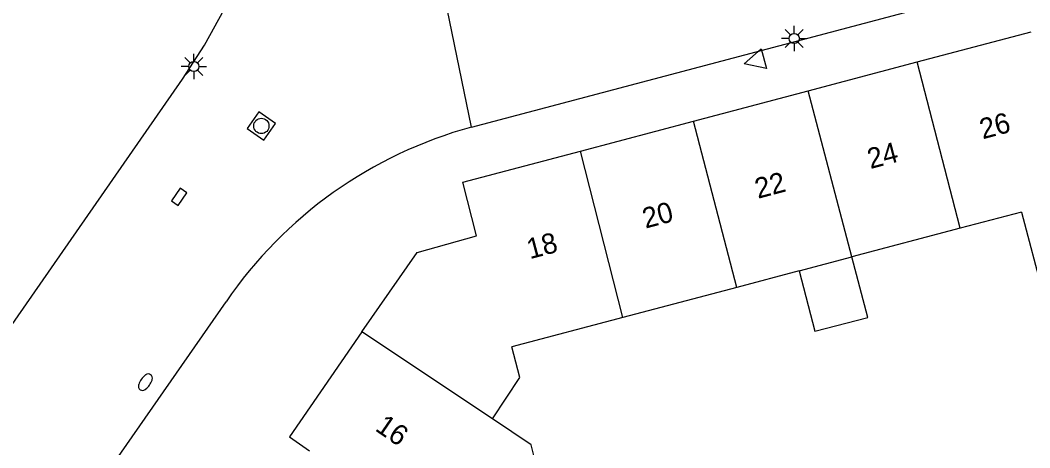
# Model space of a CAD drawing. Extents: x 136000 to 141000, y 400494 to 402006.
# Drawn here: x 137647.9 to 137697.45, y 401808.23 to 401829.21 of the extents above; entities that cross this region are included whole.
import ezdxf

# ---------------------------------------------------------------- set-up
doc = ezdxf.new("R2010")
doc.units = 0
for name, color, linetype in [('gg-anno-huisnummerreeks BGT', 7, 'Continuous'), ('gg-bbg-gedigitaliseerde bebouwing', 7, 'Continuous'), ('gg-bbg-hoofdgebouw', 7, 'Continuous'), ('gg-bbg-luifel en loopbrug', 7, 'Continuous'), ('gg-bbg-tussenscheiding', 7, 'Continuous'), ('gg-knt-verharding', 7, 'Continuous'), ('gt-grn-weggrens', 7, 'Continuous'), ('gt-symb-brandkraan', 7, 'Continuous'), ('gt-symb-kolk', 7, 'Continuous'), ('gt-symb-lichtmast', 7, 'Continuous'), ('gt-symb-rioolschacht', 7, 'Continuous'), ('gt-symb-waterafsluiter', 7, 'Continuous')]:
    doc.layers.add(name, color=color, linetype=linetype)

# ---------------------------------------------------------------- blocks, each defined once
blk = doc.blocks.new('gt0-WAFSL')
at = {"layer": 'gt-symb-waterafsluiter'}
for p, q in [((-0.5, -0.333), (0, 0.667)), ((0, 0.667), (0.5, -0.333)), ((0.5, -0.333), (-0.5, -0.333))]:
    blk.add_line(p, q, dxfattribs=at)
blk = doc.blocks.new('gt0-LMAST')
at = {"layer": 'gt-symb-lichtmast'}
for p, q in [((-0.005, 0.246), (-0.005, 0.621)), ((-0.182, 0.173), (-0.447, 0.438)), ((0.172, 0.173), (0.437, 0.438)), ((-0.255, -0.004), (-0.63, -0.004)), ((-0.182, -0.181), (-0.447, -0.446)), ((-0.005, -0.254), (-0.005, -0.629)), ((0.437, -0.446), (0.172, -0.181)), ((0.245, -0.004), (0.62, -0.004))]:
    blk.add_line(p, q, dxfattribs=at)
blk.add_circle((-0.005, -0.004), 0.25, dxfattribs=at)
blk = doc.blocks.new('gt0-BR')
at = {"layer": 'gt-symb-brandkraan'}
for centre, radius, start, end in [((-0.244, 0), 0.206, 107.5669, 252.4331), ((0.599, -2.664), 3, 106.892, 107.5669), ((0, -0.691), 0.938, 73.108, 106.892), ((-0.599, -2.664), 3, 72.4331, 73.108), ((0.244, 0), 0.206, 287.567, 72.4331), ((0.599, 2.664), 3, 252.4331, 253.108), ((0, 0.691), 0.938, 253.108, 286.8921), ((-0.599, 2.664), 3, 286.8921, 287.567)]:
    blk.add_arc(centre, radius, start, end, dxfattribs=at)
blk = doc.blocks.new('gt0-KOLK')
at = {"layer": 'gt-symb-kolk'}
blk.add_lwpolyline([(0, 0), (0.375, 0), (0.375, 0.4), (-0.375, 0.4), (-0.375, 0), (0, 0)], dxfattribs=at)
blk = doc.blocks.new('gt0-RS')
at = {"layer": 'gt-symb-rioolschacht'}
blk.add_lwpolyline([(-0.5, -0.5), (0.5, -0.5), (0.5, 0.5), (-0.5, 0.5)], close=True, dxfattribs=at)
blk.add_circle((0, 0), 0.375, dxfattribs=at)

msp = doc.modelspace()

# ---------------------------------------------------------------- linework, layer by layer
at = {"layer": 'gg-bbg-gedigitaliseerde bebouwing'}
for p, q in [((137697.042, 401819.797), (137694.029, 401818.999)), ((137694.029, 401818.999), (137688.718, 401817.593)), ((137686.125, 401816.907), (137688.718, 401817.593)), ((137686.125, 401816.907), (137683.078, 401816.1)), ((137683.078, 401816.1), (137677.471, 401814.615)), ((137677.471, 401814.615), (137672.031, 401813.175)), ((137672.981, 401808.38), (137671.078, 401809.64))]:
    msp.add_line(p, q, dxfattribs=at)
for points in [[(137697.042, 401819.797), (137698.108, 401815.768), (137700.76, 401816.47), (137699.694, 401820.499)], [(137671.078, 401809.64), (137672.427, 401811.678), (137672.031, 401813.175)], [(137669.526, 401799.445), (137673.691, 401805.487), (137672.981, 401808.38)]]:
    msp.add_lwpolyline(points, dxfattribs=at)
at = {"layer": 'gg-bbg-hoofdgebouw'}
for p, q in [((137691.927, 401827.165), (137697.519, 401828.646)), ((137686.568, 401825.747), (137691.927, 401827.165)), ((137680.947, 401824.258), (137686.568, 401825.747)), ((137675.396, 401822.789), (137680.947, 401824.258))]:
    msp.add_line(p, q, dxfattribs=at)
for points in [[(137664.67, 401813.92), (137667.39, 401817.81), (137670.3, 401818.63), (137669.62, 401821.26), (137675.396, 401822.789)], [(137664.67, 401813.92), (137661.115, 401808.759), (137662.092, 401808.08)]]:
    msp.add_lwpolyline(points, dxfattribs=at)
at = {"layer": 'gg-bbg-luifel en loopbrug'}
msp.add_lwpolyline([(137686.125, 401816.907), (137686.909, 401813.945), (137689.5, 401814.628), (137688.718, 401817.593)], dxfattribs=at)
at = {"layer": 'gg-bbg-tussenscheiding'}
for p, q in [((137694.029, 401818.999), (137691.927, 401827.165)), ((137688.718, 401817.593), (137686.568, 401825.747)), ((137683.078, 401816.1), (137680.947, 401824.258)), ((137677.471, 401814.615), (137675.396, 401822.789)), ((137671.078, 401809.64), (137664.67, 401813.92))]:
    msp.add_line(p, q, dxfattribs=at)
at = {"layer": 'gg-knt-verharding'}
for p, q in [((137670.05, 401823.96), (137702.59, 401832.578)), ((137645.408, 401797.286), (137658.002, 401815.393))]:
    msp.add_line(p, q, dxfattribs=at)
msp.add_lwpolyline([(137645.992, 401812.127), (137655.86, 401826.31), (137656.94, 401827.99), (137657.91, 401829.74), (137660.375, 401834.784)], dxfattribs=at)
msp.add_arc((137675.652, 401803.327), 21.38, 105.189, 145.6421, dxfattribs=at)
at = {"layer": 'gt-grn-weggrens'}
msp.add_line((137670.05, 401823.96), (137668.629, 401830.9), dxfattribs=at)

# ---------------------------------------------------------------- block references
at = {"layer": 'gt-symb-brandkraan', "rotation": -124.81835448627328}
msp.add_blockref('gt0-BR', (137654.041, 401811.445), dxfattribs=at)
at = {"layer": 'gt-symb-kolk', "rotation": 55.43537706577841}
msp.add_blockref('gt0-KOLK', (137655.87, 401820.423), dxfattribs=at)
at = {"layer": 'gt-symb-lichtmast'}
for p in [(137685.897, 401828.317), (137656.422, 401826.939)]:
    msp.add_blockref('gt0-LMAST', p, dxfattribs=at)
at = {"layer": 'gt-symb-rioolschacht', "rotation": 55.181645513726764}
msp.add_blockref('gt0-RS', (137659.733, 401824.019), dxfattribs=at)
at = {"layer": 'gt-symb-waterafsluiter', "rotation": 104.82810852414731}
msp.add_blockref('gt0-WAFSL', (137684.072, 401827.237), dxfattribs=at)

# ---------------------------------------------------------------- texts
at = {"layer": 'gg-anno-huisnummerreeks BGT'}
for s, rotation, p in [('26', 14.8, (137695.141, 401823.362)), ('24', 14.8, (137689.63, 401821.903)), ('22', 14.8, (137684.109, 401820.442)), ('20', 14.8, (137678.59, 401818.98)), ('18', 14.8, (137672.914, 401817.478)), ('16', 325.5, (137665.267, 401809.104))]:
    msp.add_text(s, height=1, rotation=rotation, dxfattribs=at).set_placement(p)

doc.saveas('drawing.dxf')
